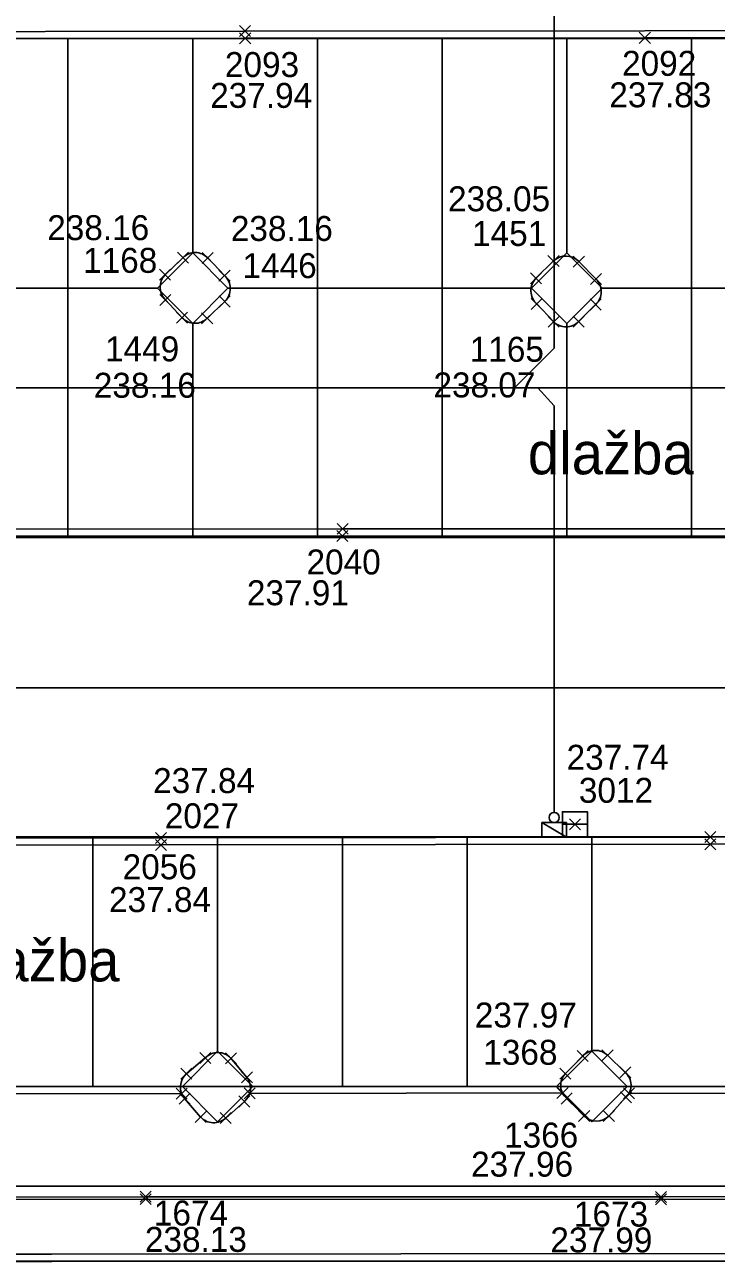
# Model space of a CAD drawing. Extents: x -264165 to -263733, y -1242319 to -1242245.
# Drawn here: x -263901.43 to -263887.58, y -1242301.5 to -1242276.71 of the extents above; entities that cross this region are included whole.
import ezdxf

# ---------------------------------------------------------------- set-up
doc = ezdxf.new("R2010")
doc.units = 0
for name, color, linetype in [('KFA_BOD_CISLO', 7, 'Continuous'), ('KFA_BOD_SYMBOL', 7, 'Continuous'), ('KFA_BOD_VYSKA', 7, 'Continuous'), ('KFA_SO_20-2_OBRUBNIKY_DOLNA_HRANA', 7, 'Continuous'), ('KFA_SO_20-2_OBRUBNIKY_HORNA_HRANA', 7, 'Continuous'), ('KFA_UV_BOD_CISLO', 7, 'Continuous'), ('KFA_UV_BOD_SYMBOL', 7, 'Continuous'), ('KFA_UV_BOD_VYSKA', 7, 'Continuous'), ('POPIS', 7, 'Continuous'), ('PROJEKT_OBRUBNIKY_KOMUNIKACIE', 7, 'Continuous'), ('PROJEKT_TDZ_VODOROVNE', 7, 'Continuous'), ('SITUACIA_DSP_2D', 7, 'Continuous'), ('SO_20-1_OBRUBNIKY_DOLNA_HRANA', 7, 'Continuous'), ('SO_20-1_OBRUBNIKY_HORNA_HRANA', 7, 'Continuous'), ('ULICNA_VPUST_POKLOP', 7, 'Continuous')]:
    doc.layers.add(name, color=color, linetype=linetype)

msp = doc.modelspace()

# ---------------------------------------------------------------- linework, layer by layer
at = {"layer": 'KFA_BOD_SYMBOL'}
for p, q in [((-263897.129, -1242276.941), (-263896.908, -1242276.721)), ((-263896.908, -1242276.941), (-263897.129, -1242276.721)), ((-263897.128, -1242277.086), (-263896.906, -1242276.866)), ((-263896.906, -1242277.086), (-263897.128, -1242276.866)), ((-263889.117, -1242277.079), (-263888.895, -1242276.857)), ((-263888.895, -1242277.079), (-263889.117, -1242276.857)), ((-263898.372, -1242281.481), (-263898.151, -1242281.261)), ((-263898.151, -1242281.481), (-263898.372, -1242281.261)), ((-263897.878, -1242281.49), (-263897.657, -1242281.269)), ((-263897.657, -1242281.49), (-263897.878, -1242281.269)), ((-263890.948, -1242281.549), (-263890.726, -1242281.328)), ((-263890.726, -1242281.549), (-263890.948, -1242281.328)), ((-263890.44, -1242281.563), (-263890.219, -1242281.343)), ((-263890.219, -1242281.563), (-263890.44, -1242281.343)), ((-263898.732, -1242281.826), (-263898.511, -1242281.606)), ((-263898.511, -1242281.826), (-263898.732, -1242281.606)), ((-263897.541, -1242281.843), (-263897.32, -1242281.623)), ((-263897.32, -1242281.843), (-263897.541, -1242281.623)), ((-263891.3, -1242281.897), (-263891.079, -1242281.676)), ((-263891.079, -1242281.897), (-263891.3, -1242281.676)), ((-263890.098, -1242281.91), (-263889.877, -1242281.69)), ((-263889.877, -1242281.91), (-263890.098, -1242281.69)), ((-263898.724, -1242282.329), (-263898.503, -1242282.109)), ((-263898.503, -1242282.329), (-263898.724, -1242282.109)), ((-263897.536, -1242282.362), (-263897.315, -1242282.14)), ((-263897.315, -1242282.362), (-263897.536, -1242282.14)), ((-263891.284, -1242282.409), (-263891.062, -1242282.188)), ((-263891.062, -1242282.409), (-263891.284, -1242282.188)), ((-263890.103, -1242282.423), (-263889.882, -1242282.201)), ((-263889.882, -1242282.423), (-263890.103, -1242282.201)), ((-263898.391, -1242282.687), (-263898.17, -1242282.465)), ((-263898.17, -1242282.687), (-263898.391, -1242282.465)), ((-263897.889, -1242282.698), (-263897.667, -1242282.477)), ((-263897.667, -1242282.698), (-263897.889, -1242282.477)), ((-263890.943, -1242282.769), (-263890.722, -1242282.549)), ((-263890.722, -1242282.769), (-263890.943, -1242282.549)), ((-263890.446, -1242282.764), (-263890.225, -1242282.542)), ((-263890.225, -1242282.764), (-263890.446, -1242282.542)), ((-263895.179, -1242287.063), (-263894.958, -1242286.843)), ((-263894.958, -1242287.063), (-263895.179, -1242286.843)), ((-263895.175, -1242286.917), (-263894.954, -1242286.697)), ((-263894.954, -1242286.917), (-263895.175, -1242286.697)), ((-263898.816, -1242293.113), (-263898.595, -1242292.891)), ((-263898.595, -1242293.113), (-263898.816, -1242292.891)), ((-263898.816, -1242293.252), (-263898.595, -1242293.032)), ((-263898.595, -1242293.252), (-263898.816, -1242293.032)), ((-263887.806, -1242293.238), (-263887.584, -1242293.018)), ((-263887.584, -1242293.238), (-263887.806, -1242293.018)), ((-263887.804, -1242293.095), (-263887.583, -1242292.873)), ((-263887.583, -1242293.095), (-263887.804, -1242292.873)), ((-263897.927, -1242297.519), (-263897.706, -1242297.299)), ((-263897.706, -1242297.519), (-263897.927, -1242297.299)), ((-263897.413, -1242297.525), (-263897.192, -1242297.305)), ((-263897.192, -1242297.525), (-263897.413, -1242297.305)), ((-263890.362, -1242297.484), (-263890.141, -1242297.262)), ((-263890.141, -1242297.484), (-263890.362, -1242297.262)), ((-263889.866, -1242297.468), (-263889.644, -1242297.247)), ((-263889.644, -1242297.468), (-263889.866, -1242297.247)), ((-263898.305, -1242297.836), (-263898.084, -1242297.615)), ((-263898.084, -1242297.836), (-263898.305, -1242297.615)), ((-263897.09, -1242297.91), (-263896.869, -1242297.69)), ((-263896.869, -1242297.91), (-263897.09, -1242297.69)), ((-263890.712, -1242297.836), (-263890.491, -1242297.615)), ((-263890.491, -1242297.836), (-263890.712, -1242297.615)), ((-263889.509, -1242297.809), (-263889.288, -1242297.589)), ((-263889.288, -1242297.809), (-263889.509, -1242297.589)), ((-263898.398, -1242298.237), (-263898.177, -1242298.015)), ((-263898.177, -1242298.237), (-263898.398, -1242298.015)), ((-263897.035, -1242298.231), (-263896.813, -1242298.011)), ((-263896.813, -1242298.231), (-263897.035, -1242298.011)), ((-263890.768, -1242298.222), (-263890.546, -1242298.002)), ((-263890.546, -1242298.222), (-263890.768, -1242298.002)), ((-263889.436, -1242298.23), (-263889.215, -1242298.008)), ((-263889.215, -1242298.23), (-263889.436, -1242298.008)), ((-263898.34, -1242298.333), (-263898.119, -1242298.113)), ((-263898.119, -1242298.333), (-263898.34, -1242298.113)), ((-263897.141, -1242298.393), (-263896.92, -1242298.171)), ((-263896.92, -1242298.393), (-263897.141, -1242298.171)), ((-263890.683, -1242298.333), (-263890.462, -1242298.112)), ((-263890.462, -1242298.333), (-263890.683, -1242298.112)), ((-263889.496, -1242298.309), (-263889.274, -1242298.088)), ((-263889.274, -1242298.309), (-263889.496, -1242298.088)), ((-263898.019, -1242298.704), (-263897.799, -1242298.484)), ((-263897.799, -1242298.704), (-263898.019, -1242298.484)), ((-263897.518, -1242298.725), (-263897.296, -1242298.504)), ((-263897.296, -1242298.725), (-263897.518, -1242298.504)), ((-263890.334, -1242298.683), (-263890.112, -1242298.461)), ((-263890.112, -1242298.683), (-263890.334, -1242298.461)), ((-263889.839, -1242298.686), (-263889.617, -1242298.465)), ((-263889.617, -1242298.686), (-263889.839, -1242298.465)), ((-263899.123, -1242300.301), (-263898.902, -1242300.079)), ((-263898.902, -1242300.301), (-263899.123, -1242300.079)), ((-263899.123, -1242300.35), (-263898.902, -1242300.13)), ((-263898.902, -1242300.35), (-263899.123, -1242300.13)), ((-263888.795, -1242300.306), (-263888.573, -1242300.085)), ((-263888.573, -1242300.306), (-263888.795, -1242300.085)), ((-263888.795, -1242300.356), (-263888.573, -1242300.134)), ((-263888.573, -1242300.356), (-263888.795, -1242300.134))]:
    msp.add_line(p, q, dxfattribs=at)
at = {"layer": 'KFA_SO_20-2_OBRUBNIKY_DOLNA_HRANA'}
for points in [[(-263816.727, -1242276.824), (-263824.896, -1242276.832), (-263841.932, -1242276.838), (-263860.969, -1242276.825), (-263872.991, -1242276.822), (-263881, -1242276.818), (-263897.019, -1242276.831), (-263905.035, -1242276.846), (-263913.057, -1242276.848), (-263917.557, -1242276.899)], [(-263817.074, -1242276.98), (-263824.904, -1242276.976), (-263831.918, -1242276.976), (-263841.931, -1242276.979), (-263850.949, -1242276.976), (-263860.958, -1242276.969), (-263872.991, -1242276.965), (-263880.996, -1242276.964), (-263889.006, -1242276.968), (-263897.017, -1242276.976), (-263905.035, -1242276.99), (-263913.048, -1242276.994), (-263917.092, -1242277.009)], [(-263819.103, -1242286.786), (-263819.439, -1242286.959), (-263828.996, -1242286.962), (-263838.005, -1242286.965), (-263845.009, -1242286.967), (-263853.017, -1242286.968), (-263861.032, -1242286.966), (-263868.037, -1242286.96), (-263877.037, -1242286.952), (-263886.053, -1242286.951), (-263895.068, -1242286.953), (-263904.067, -1242286.955), (-263910.084, -1242286.961), (-263917.346, -1242286.958)], [(-263819.419, -1242286.819), (-263828.995, -1242286.822), (-263838.007, -1242286.821), (-263845.022, -1242286.826), (-263853.012, -1242286.818), (-263861.03, -1242286.825), (-263868.034, -1242286.816), (-263877.043, -1242286.812), (-263886.05, -1242286.81), (-263895.064, -1242286.807), (-263904.07, -1242286.816), (-263910.08, -1242286.821), (-263917.062, -1242286.824)], [(-263817.492, -1242292.982), (-263829.632, -1242292.973), (-263839.651, -1242292.963), (-263849.653, -1242292.97), (-263858.67, -1242292.978), (-263866.671, -1242292.969), (-263877.683, -1242292.971), (-263887.693, -1242292.984), (-263898.705, -1242293.002), (-263909.705, -1242293.003), (-263917.41, -1242292.997)], [(-263817.431, -1242293.129), (-263829.63, -1242293.121), (-263839.649, -1242293.107), (-263849.656, -1242293.117), (-263858.667, -1242293.124), (-263866.668, -1242293.115), (-263877.682, -1242293.116), (-263887.695, -1242293.128), (-263898.705, -1242293.142), (-263909.706, -1242293.151), (-263917.057, -1242293.143)]]:
    msp.add_lwpolyline(points, dxfattribs=at)
at = {"layer": 'KFA_SO_20-2_OBRUBNIKY_HORNA_HRANA'}
for p, q in [((-263898.262, -1242281.371), (-263898.622, -1242281.716)), ((-263897.768, -1242281.379), (-263897.431, -1242281.733)), ((-263891.189, -1242281.786), (-263890.837, -1242281.438)), ((-263890.329, -1242281.453), (-263889.987, -1242281.8)), ((-263898.613, -1242282.219), (-263898.28, -1242282.576)), ((-263897.426, -1242282.251), (-263897.778, -1242282.587)), ((-263890.833, -1242282.659), (-263891.173, -1242282.298)), ((-263889.992, -1242282.312), (-263890.335, -1242282.653)), ((-263898.194, -1242297.725), (-263897.817, -1242297.409)), ((-263897.302, -1242297.415), (-263896.98, -1242297.8)), ((-263890.601, -1242297.725), (-263890.252, -1242297.373)), ((-263889.755, -1242297.357), (-263889.399, -1242297.699)), ((-263898.287, -1242298.126), (-263904.367, -1242298.122)), ((-263897.909, -1242298.594), (-263898.23, -1242298.223)), ((-263897.407, -1242298.614), (-263897.03, -1242298.282)), ((-263890.657, -1242298.112), (-263896.924, -1242298.121)), ((-263890.223, -1242298.572), (-263890.573, -1242298.222)), ((-263889.385, -1242298.198), (-263889.728, -1242298.575)), ((-263883.278, -1242298.135), (-263889.325, -1242298.119))]:
    msp.add_line(p, q, dxfattribs=at)
for points in [[(-263818.454, -1242300.127), (-263820.114, -1242300.153), (-263830.062, -1242300.171), (-263840.06, -1242300.171), (-263850.054, -1242300.16), (-263860.027, -1242300.174), (-263870.031, -1242300.18), (-263880.008, -1242300.187), (-263888.684, -1242300.195), (-263899.013, -1242300.19), (-263908.987, -1242300.212), (-263915.978, -1242300.22), (-263917.721, -1242300.207)], [(-263818.504, -1242300.177), (-263820.112, -1242300.193), (-263830.062, -1242300.221), (-263840.06, -1242300.221), (-263850.054, -1242300.21), (-263860.027, -1242300.224), (-263870.031, -1242300.23), (-263880.008, -1242300.237), (-263888.684, -1242300.245), (-263899.013, -1242300.24), (-263908.987, -1242300.262), (-263915.978, -1242300.27), (-263917.654, -1242300.257)]]:
    msp.add_lwpolyline(points, dxfattribs=at)
for centre, major_axis, ratio, start_param, end_param in [((-263898.019, -1242281.612), (-0.312, 0.142), 0.999678, 4.317685, 5.92757), ((-263890.59, -1242281.701), (-0.35, 0.087), 0.998932, 4.145925, 5.708033), ((-263898.364, -1242281.963), (0.326, -0.146), 0.999882, 2.7981, 4.359515), ((-263897.667, -1242281.994), (0.234, 0.264), 0.999735, 4.622, 6.273912), ((-263890.935, -1242282.034), (0.149, -0.323), 0.999687, 3.506909, 5.116807), ((-263890.234, -1242282.054), (0.287, 0.208), 0.999705, 4.838558, 6.453799), ((-263898.024, -1242282.339), (0.304, -0.172), 0.999435, 4.403965, 6.008436), ((-263890.587, -1242282.412), (0.325, 0.128), 0.999857, 3.553594, 5.143094), ((-263897.562, -1242297.656), (-0.355, -0.004), 0.996302, 3.878351, 5.501226), ((-263889.996, -1242297.602), (-0.341, -0.044), 0.998016, 3.809101, 5.423751), ((-263897.952, -1242297.992), (-0.138, -0.334), 0.997968, 4.268658, 5.795447), ((-263897.261, -1242298.014), (0.3, 0.187), 0.999969, 4.867103, 6.378853), ((-263890.344, -1242297.96), (-0.133, -0.322), 0.998926, 4.364518, 5.956906), ((-263889.623, -1242297.955), (-0.039, 0.338), 0.99974, 3.800291, 5.448448), ((-263897.648, -1242298.355), (0.332, -0.121), 0.999234, 4.233347, 5.811775), ((-263889.974, -1242298.32), (0.342, -0.091), 0.99971, 4.192583, 5.74077)]:
    msp.add_ellipse(centre, major_axis=major_axis, ratio=ratio, start_param=start_param, end_param=end_param, dxfattribs=at)
at = {"layer": 'KFA_UV_BOD_SYMBOL'}
for p, q in [((-263890.519, -1242292.839), (-263890.297, -1242292.617)), ((-263890.297, -1242292.839), (-263890.519, -1242292.617))]:
    msp.add_line(p, q, dxfattribs=at)
at = {"layer": 'PROJEKT_OBRUBNIKY_KOMUNIKACIE'}
for p, q in [((-263917.08, -1242276.982), (-263817.068, -1242276.982)), ((-263819.568, -1242286.982), (-263917.08, -1242286.982)), ((-263817.19, -1242292.982), (-263917.08, -1242292.982)), ((-263815.601, -1242297.982), (-263917.08, -1242297.982)), ((-263816.308, -1242299.982), (-263918.049, -1242299.982)), ((-263914.08, -1242301.482), (-263815.822, -1242301.482))]:
    msp.add_line(p, q, dxfattribs=at)
for points in [[(-263898.068, -1242281.275), (-263897.361, -1242281.982), (-263898.068, -1242282.689), (-263898.775, -1242281.982), (-263898.068, -1242281.275)], [(-263890.568, -1242281.275), (-263889.861, -1242281.982), (-263890.568, -1242282.689), (-263891.275, -1242281.982), (-263890.568, -1242281.275)], [(-263890.568, -1242281.275), (-263889.861, -1242281.982), (-263890.568, -1242282.689), (-263891.275, -1242281.982), (-263890.568, -1242281.275)], [(-263897.568, -1242297.275), (-263896.861, -1242297.982), (-263897.568, -1242298.689), (-263898.275, -1242297.982), (-263897.568, -1242297.275)], [(-263890.068, -1242297.275), (-263889.361, -1242297.982), (-263890.068, -1242298.689), (-263890.775, -1242297.982), (-263890.068, -1242297.275)], [(-263890.068, -1242297.275), (-263889.361, -1242297.982), (-263890.068, -1242298.689), (-263890.775, -1242297.982), (-263890.068, -1242297.275)]]:
    msp.add_lwpolyline(points, dxfattribs=at)
at = {"layer": 'PROJEKT_TDZ_VODOROVNE'}
for p, q in [((-263900.568, -1242281.982), (-263900.568, -1242276.982)), ((-263898.068, -1242281.275), (-263898.068, -1242276.982)), ((-263895.568, -1242281.982), (-263895.568, -1242276.982)), ((-263893.068, -1242281.982), (-263893.068, -1242276.982)), ((-263890.568, -1242281.275), (-263890.568, -1242276.982)), ((-263888.068, -1242281.982), (-263888.068, -1242276.982)), ((-263898.775, -1242281.982), (-263917.08, -1242281.982)), ((-263900.568, -1242286.982), (-263900.568, -1242281.982)), ((-263891.275, -1242281.982), (-263897.361, -1242281.982)), ((-263895.568, -1242286.982), (-263895.568, -1242281.982)), ((-263893.068, -1242286.982), (-263893.068, -1242281.982)), ((-263883.775, -1242281.982), (-263889.861, -1242281.982)), ((-263888.068, -1242286.982), (-263888.068, -1242281.982)), ((-263898.068, -1242286.982), (-263898.068, -1242282.689)), ((-263890.568, -1242286.982), (-263890.568, -1242282.689)), ((-263819.531, -1242289.994), (-263917.477, -1242289.994)), ((-263900.068, -1242297.982), (-263900.068, -1242292.982)), ((-263897.568, -1242297.275), (-263897.568, -1242292.982)), ((-263895.068, -1242297.982), (-263895.068, -1242292.982)), ((-263892.568, -1242297.982), (-263892.568, -1242292.982)), ((-263890.068, -1242297.275), (-263890.068, -1242292.982))]:
    msp.add_line(p, q, dxfattribs=at)
at = {"layer": 'SITUACIA_DSP_2D'}
for p, q in [((-263890.824, -1242271.473), (-263890.824, -1242283.187)), ((-263890.824, -1242283.187), (-263891.619, -1242283.982)), ((-263871.324, -1242283.982), (-263903.413, -1242283.982)), ((-263890.824, -1242284.343), (-263891.149, -1242283.982)), ((-263890.824, -1242292.492), (-263890.824, -1242284.343)), ((-263891.074, -1242292.693), (-263890.574, -1242292.693)), ((-263891.074, -1242292.983), (-263891.074, -1242292.693)), ((-263891.074, -1242292.693), (-263890.574, -1242292.983)), ((-263891.074, -1242292.693), (-263890.574, -1242292.983)), ((-263890.574, -1242292.693), (-263891.074, -1242292.693)), ((-263890.574, -1242292.693), (-263890.574, -1242292.983)), ((-263890.574, -1242292.983), (-263890.574, -1242292.693)), ((-263890.574, -1242292.983), (-263891.074, -1242292.983)), ((-263815.601, -1242297.982), (-263917.08, -1242297.982)), ((-263816.308, -1242299.982), (-263918.049, -1242299.982)), ((-263914.08, -1242301.482), (-263815.822, -1242301.482))]:
    msp.add_line(p, q, dxfattribs=at)
for points in [[(-263898.068, -1242281.275), (-263897.361, -1242281.982), (-263898.068, -1242282.689), (-263898.775, -1242281.982)], [(-263890.568, -1242281.275), (-263889.861, -1242281.982), (-263890.568, -1242282.689), (-263891.275, -1242281.982)], [(-263890.568, -1242281.275), (-263889.861, -1242281.982), (-263890.568, -1242282.689), (-263891.275, -1242281.982)], [(-263897.568, -1242297.275), (-263896.861, -1242297.982), (-263897.568, -1242298.689), (-263898.275, -1242297.982)], [(-263890.068, -1242297.275), (-263889.361, -1242297.982), (-263890.068, -1242298.689), (-263890.775, -1242297.982)], [(-263890.068, -1242297.275), (-263889.361, -1242297.982), (-263890.068, -1242298.689), (-263890.775, -1242297.982)]]:
    msp.add_lwpolyline(points, close=True, dxfattribs=at)
msp.add_circle((-263890.824, -1242292.592), 0.1, dxfattribs=at)
at = {"layer": 'SO_20-1_OBRUBNIKY_DOLNA_HRANA'}
msp.add_lwpolyline([(-263913.884, -1242301.489), (-263907.893, -1242301.489), (-263900.89, -1242301.488), (-263893.898, -1242301.483), (-263886.917, -1242301.473), (-263879.922, -1242301.465), (-263872.91, -1242301.469), (-263865.929, -1242301.465), (-263859.932, -1242301.473), (-263850.941, -1242301.471), (-263843.947, -1242301.471), (-263836.942, -1242301.481), (-263829.943, -1242301.484), (-263823.945, -1242301.487), (-263818.452, -1242301.495), (-263816.42, -1242301.504)], dxfattribs=at)
at = {"layer": 'SO_20-1_OBRUBNIKY_HORNA_HRANA'}
msp.add_lwpolyline([(-263913.884, -1242301.344), (-263907.893, -1242301.343), (-263900.896, -1242301.344), (-263893.895, -1242301.338), (-263886.916, -1242301.328), (-263879.921, -1242301.324), (-263872.911, -1242301.324), (-263865.928, -1242301.325), (-263859.931, -1242301.327), (-263850.935, -1242301.324), (-263843.941, -1242301.331), (-263836.939, -1242301.332), (-263829.941, -1242301.342), (-263823.94, -1242301.343), (-263818.456, -1242301.352), (-263816.413, -1242301.358)], dxfattribs=at)
at = {"layer": 'ULICNA_VPUST_POKLOP'}
msp.add_line((-263890.408, -1242292.728), (-263890.408, -1242292.728), dxfattribs=at)
msp.add_lwpolyline([(-263890.658, -1242292.728), (-263890.658, -1242292.478), (-263890.158, -1242292.478), (-263890.158, -1242292.978), (-263890.658, -1242292.978), (-263890.658, -1242292.728), (-263890.158, -1242292.728)], dxfattribs=at)

# ---------------------------------------------------------------- texts
at = {"layer": 'KFA_BOD_CISLO'}
for s, p in [('2092', (-263889.463, -1242277.729)), ('2093', (-263897.423, -1242277.753)), ('1451', (-263892.47, -1242281.138)), ('1168', (-263900.266, -1242281.677)), ('1446', (-263897.07, -1242281.783)), ('1449', (-263899.826, -1242283.451)), ('1165', (-263892.516, -1242283.459)), ('2040', (-263895.787, -1242287.721)), ('2027', (-263898.627, -1242292.807)), ('2056', (-263899.472, -1242293.83)), ('1368', (-263892.245, -1242297.547)), ('1366', (-263891.828, -1242299.206)), ('1674', (-263898.846, -1242300.768)), ('1673', (-263890.428, -1242300.789))]:
    msp.add_text(s, height=0.5, dxfattribs=at).set_placement(p)
at = {"layer": 'KFA_BOD_VYSKA'}
for s, p in [('237.94', (-263897.718, -1242278.371)), ('237.83', (-263889.718, -1242278.359)), ('238.05', (-263892.95, -1242280.443)), ('238.16', (-263900.984, -1242281.022)), ('238.16', (-263897.304, -1242281.038)), ('238.16', (-263900.05, -1242284.18)), ('238.07', (-263893.243, -1242284.173)), ('237.91', (-263896.982, -1242288.338)), ('237.84', (-263898.862, -1242292.102)), ('237.84', (-263899.745, -1242294.487)), ('237.97', (-263892.414, -1242296.8)), ('237.96', (-263892.489, -1242299.789)), ('238.13', (-263899.026, -1242301.296)), ('237.99', (-263890.9, -1242301.307))]:
    msp.add_text(s, height=0.5, dxfattribs=at).set_placement(p)
at = {"layer": 'KFA_UV_BOD_CISLO'}
msp.add_text('3012', height=0.5, dxfattribs=at).set_placement((-263890.329, -1242292.297))
at = {"layer": 'KFA_UV_BOD_VYSKA'}
msp.add_text('237.74', height=0.5, dxfattribs=at).set_placement((-263890.575, -1242291.635))
at = {"layer": 'POPIS'}
for p in [(-263891.351, -1242285.714), (-263902.86, -1242295.876)]:
    msp.add_text('dlažba', height=0.8438, dxfattribs=at).set_placement(p)

doc.saveas('drawing.dxf')
